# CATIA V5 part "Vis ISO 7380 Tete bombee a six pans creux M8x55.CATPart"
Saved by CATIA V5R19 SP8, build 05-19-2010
Part number: Vis ISO 7380 Tete bombee a six pans creux M8x55
Nomenclature: 12
Source: Unknown
Description: PART-pn48560052-DESC
Material "Acier": density 7860 kg/m3, Young's modulus 2e+11 Pa, Poisson ratio 0.266, thermal expansion 1.17e-05 1/K
Material "Acier": density 7860 kg/m3, Young's modulus 2e+11 Pa, Poisson ratio 0.266, thermal expansion 1.17e-05 1/K
Bounding box of the stored display mesh (mm): x -4.4 to 50, y -7 to 7, z -7 to 7
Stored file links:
  C:\Users\rphgr\Desktop\0_Tapis_TC520B_vitesse\Vis ISO 7380 Tete bombee a six pans creux M8x55.CATPart
  C:\Program Files\Dassault Systemes\B19\win_b64\reffiles\standard\MetricThickPitch.txt
  D:\Programmes\DassaultSysteme\win_b64\startup\materials\French\Catalog.CATMaterial
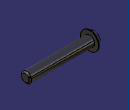
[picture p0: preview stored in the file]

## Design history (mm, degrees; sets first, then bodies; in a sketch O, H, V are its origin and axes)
AxisSystem1: origin (0, 0, 0), X (1, 0, 0), Y (0, 1, 0), Z (0, 0, 1)
Body1 "Tête" (main body), material "Acier"
  Solid1 "pn48560052": solid without history
  Split1: SplitPlane face of Solid1
Body2, material "Acier"
  Sketch1 on XY plane of AxisSystem1, origin (0, 0, 0), H (1, 0, 0), V (0, 1, 0)
    line L1 (50, 0) -> (50, 4)
    line L2 (50, 4) -> (0, 4)
    line L3 (0, 4) -> (0, 0)
    axis line L4 (0, 0) -> (56.1618, 0)
    reference intersected line E1 (0, 7) -> (0, -7) from face of Split1
    distance L1 E1 = 50
    "Radius" L2 L4 = 4
    horizontal: L2 H, L4 H
    vertical: L1 V, L3 V
  Shaft1: profile Sketch1, axis Sketch1.L4, angle 360
  Thread1: "M8", diameter 8, depth 12, pitch 1.25, on face of Shaft1 from Sketch1.L2, from face of Shaft1 from Sketch1.L1
  Chamfer1: length 1, angle 45, on edge [face of Shaft1 from Sketch1.L2 | face of Shaft1 from Sketch1.L1]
